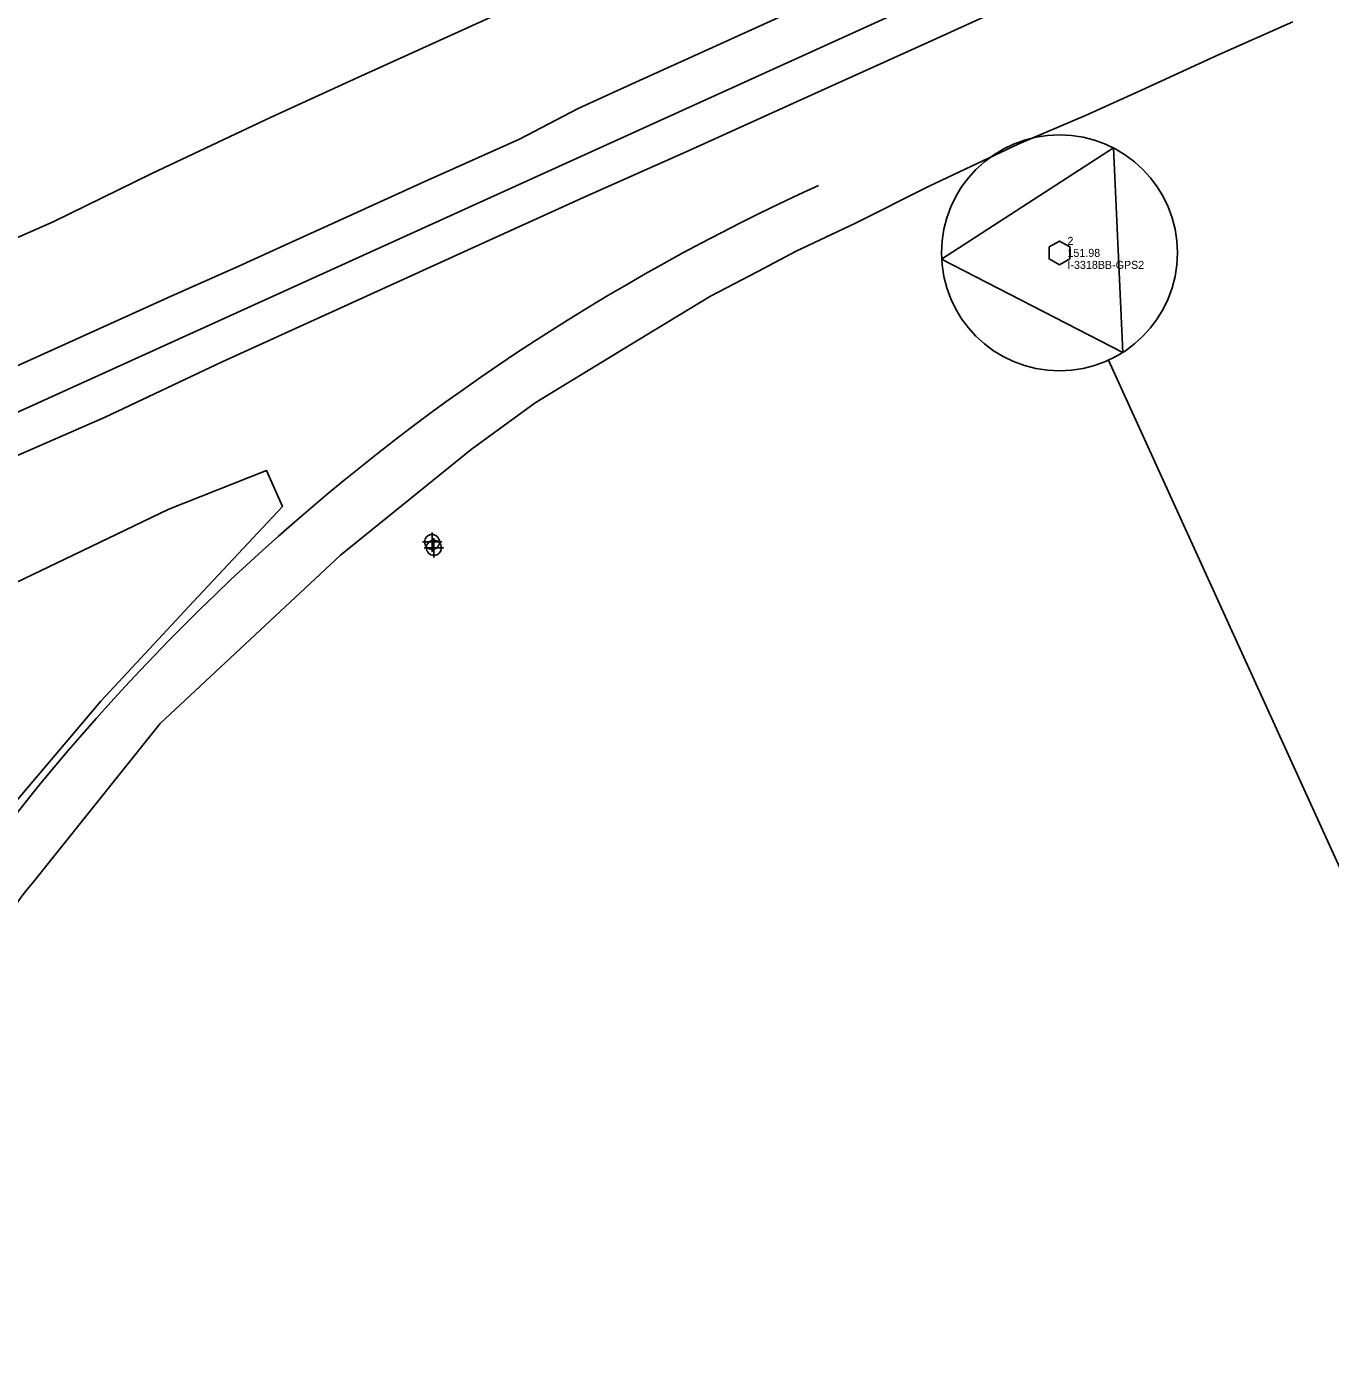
# Model space of a CAD drawing. Extents: x 2243531 to 2252747, y 658714 to 667210.
# Drawn here: x 2248142 to 2248549.2, y 662697.8 to 663115.4 of the extents above; entities that cross this region are included whole.
import ezdxf

# ---------------------------------------------------------------- set-up
doc = ezdxf.new("R2010")
doc.units = 0
for name, color, linetype in [('CTL GPS Vertical CELL', 7, 'Continuous'), ('CTL GPS Vertical Cogo Comment', 7, 'Continuous'), ('CTL GPS Vertical Cogo Elevation', 7, 'Continuous'), ('CTL GPS Vertical Cogo Number', 7, 'Continuous'), ('CTL NGS Horizontal CELL', 7, 'Continuous'), ('Exist DTM Regular Point CELL', 7, 'Continuous'), ('Exist Roads EOP', 7, 'Continuous'), ('Prop Horizontal Alignment', 7, 'Continuous')]:
    doc.layers.add(name, color=color, linetype=linetype)

msp = doc.modelspace()

# ---------------------------------------------------------------- linework, layer by layer
at = {"layer": 'CTL GPS Vertical CELL'}
msp.add_line((2248464.61, 663044.75), (2248464.61, 663044.75), dxfattribs=at)
msp.add_lwpolyline([(2248461.38, 663046.62), (2248464.63, 663048.43), (2248467.88, 663046.65), (2248467.83, 663042.92), (2248464.58, 663041.03), (2248461.38, 663042.85)], close=True, dxfattribs=at)
at = {"layer": 'CTL NGS Horizontal CELL'}
for p, q in [((2248464.61, 663044.75), (2248464.61, 663044.75)), ((2248479.9, 663011.2), (2248656.03, 662624.68))]:
    msp.add_line(p, q, dxfattribs=at)
msp.add_lwpolyline([(2248427.74, 663042.82), (2248484.39, 663013.58), (2248481.52, 663077.52), (2248427.74, 663042.82)], dxfattribs=at)
msp.add_circle((2248464.61, 663044.75), 36.87, dxfattribs=at)
at = {"layer": 'Exist DTM Regular Point CELL'}
for points in [[(2248268.61, 662957.44), (2248268.61, 662951.44), (2248268.61, 662954.44), (2248271.61, 662954.44), (2248265.61, 662954.44)], [(2248269.19, 662955.61), (2248269.19, 662949.61), (2248269.19, 662952.61), (2248272.19, 662952.61), (2248266.19, 662952.61)]]:
    msp.add_lwpolyline(points, dxfattribs=at)
for centre in [(2248268.61, 662954.44), (2248269.19, 662952.61)]:
    msp.add_circle(centre, 2.34, dxfattribs=at)
at = {"layer": 'Exist Roads EOP'}
msp.add_line((2248144.13, 662848.25), (2248142, 662845.73), dxfattribs=at)
for points in [[(2247790.71, 662890.62), (2247805.57, 662898.29), (2247836.78, 662912.86), (2247861.63, 662923.16), (2247885.32, 662933.83), (2247909.61, 662945.06), (2247935.04, 662956.66), (2247966.34, 662970.9), (2247994.49, 662983.87), (2248025.59, 662998.19), (2248058.08, 663012.97), (2248088.08, 663026.44), (2248119.82, 663041.08), (2248150.21, 663054.44), (2248181.1, 663069.6), (2248218.38, 663087.19), (2248245.39, 663099.49), (2248287.88, 663118.8), (2248325.22, 663134.87), (2248357.59, 663149.14), (2248375.51, 663157.12), (2248384.78, 663161.44)], [(2248461.34, 663127.8), (2248423.69, 663110.61), (2248387, 663094.02), (2248349.12, 663076.79), (2248316.15, 663062.19), (2248279.66, 663045.57), (2248238.72, 663026.91), (2248203.09, 663010.67), (2248166.49, 662993.47), (2248131.09, 662977.98), (2248093.34, 662960.9), (2248060.54, 662946.01), (2248024.51, 662929.58), (2247987.81, 662912.88), (2247953.6, 662897.46), (2247911.13, 662878.2), (2247878.83, 662863.52), (2247842.91, 662848.25), (2247815.2, 662835.56)], [(2248395.93, 663126.99), (2248357.39, 663109.43), (2248332.32, 663098.06), (2248314.24, 663089.89), (2248295.97, 663080.25), (2248266.35, 663067), (2248241.87, 663055.93), (2248223.8, 663047.68), (2248208.24, 663040.58), (2248187.12, 663031.22), (2248158.39, 663018.25), (2248142.04, 663010.79), (2248123.7, 663002.54)], [(2248183.64, 662897.67), (2248239.99, 662950.3), (2248280.86, 662983.37), (2248300.78, 662997.93), (2248310.76, 663003.9), (2248335.48, 663019.02), (2248355.64, 663031.22), (2248370.44, 663038.88), (2248382.4, 663045.32), (2248400.93, 663054.03), (2248423.87, 663065.55), (2248451.93, 663078.83), (2248472.77, 663087.72), (2248490.23, 663095.56), (2248514.52, 663106.74), (2248537.52, 663116.93)], [(2248183.64, 662897.67), (2248239.99, 662950.3), (2248280.86, 662983.37), (2248300.78, 662997.93), (2248310.76, 663003.9), (2248335.48, 663019.02), (2248355.64, 663031.22), (2248370.44, 663038.88), (2248382.4, 663045.32), (2248400.93, 663054.03), (2248423.87, 663065.55), (2248451.93, 663078.83), (2248472.77, 663087.72), (2248490.23, 663095.56), (2248514.52, 663106.74), (2248537.52, 663116.93)], [(2247831.65, 662802.33), (2247858.38, 662814.46), (2247890.52, 662828.54), (2247929.75, 662846.07), (2247971.89, 662864.9), (2248016.34, 662884.69), (2248053.87, 662901.09), (2248085.69, 662916.48), (2248123.17, 662934.34), (2248153.89, 662949.09), (2248186.42, 662964.72), (2248216.92, 662976.74), (2248221.9, 662965.48), (2248194.06, 662935.8), (2248165.12, 662904.72)], [(2248128.89, 662862.01), (2248165.12, 662904.72)], [(2248144.13, 662848.25), (2248183.64, 662897.67)]]:
    msp.add_lwpolyline(points, dxfattribs=at)
msp.add_ellipse((2248728.98, 662396.71), major_axis=(-514.69, -532.36), ratio=0.998008, start_param=4.827674, end_param=4.935997, dxfattribs=at)
at = {"layer": 'Prop Horizontal Alignment'}
msp.add_line((2247500.8, 662705.02), (2249793.08, 663746.29), dxfattribs=at)
msp.add_arc((2248668.56, 662451.26), 675, 114.43013, 150.99406, dxfattribs=at)

# ---------------------------------------------------------------- texts
at = {"layer": 'CTL GPS Vertical Cogo Comment'}
msp.add_text('I-3318BB-GPS2', height=2.5, dxfattribs=at).set_placement((2248467.11, 663039.75))
at = {"layer": 'CTL GPS Vertical Cogo Elevation'}
msp.add_text('151.98', height=2.5, dxfattribs=at).set_placement((2248467.11, 663043.5))
at = {"layer": 'CTL GPS Vertical Cogo Number'}
msp.add_text('2', height=2.5, dxfattribs=at).set_placement((2248467.11, 663047.25))

doc.saveas('drawing.dxf')
